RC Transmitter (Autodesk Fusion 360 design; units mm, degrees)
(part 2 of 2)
extrude "Extrusion2" cut of existing geometry blind -0.1
extrude "Extrusion3" cut of existing geometry blind -0.1
extrude "Extrusion4" cut of existing geometry blind -0.1
move "Verschieben1"
move "Verschieben2"
move "Verschieben3"
move "Verschieben4"
move "Verschieben5"
move "Verschieben6"
move_face "Fläche verschieben"
move "Verschieben7"
move "Verschieben8"
position "Position1"
sketch "Skizze1" plane through (0, 0, 23.05) normal (0, 0, 1) x axis (-1, 0, 0)
  line L1 (299.8082, 67.7452) -> (287.93, 79.6234)
  line L2 (300.1011, -67.1335) -> (300.1011, 67.0381)
  line L3 (287.894, -79.7548) -> (299.8082, -67.8406)
  line L4 (211.6011, -80.0477) -> (287.1869, -80.0477)
  line L5 (211.6011, -82.3739) -> (211.6011, -80.0477)
  line L6 (289.6007, -82.3739) -> (211.6011, -82.3739)
  line L7 (302.4261, -69.5484) -> (289.6007, -82.3739)
  line L8 (302.4261, 69.203) -> (302.4261, -69.5484)
  line L9 (289.3519, 82.2773) -> (302.4261, 69.203)
  line L10 (120.6004, 82.2773) -> (289.3519, 82.2773)
  line L11 (107.7773, 69.4542) -> (120.6004, 82.2773)
  line L12 (107.7773, -69.2973) -> (107.7773, 69.4542)
  line L13 (120.8492, -82.3739) -> (107.7773, -69.2973)
  line L14 (198.6011, -82.3739) -> (120.8492, -82.3739)
  line L15 (198.6011, -80.0477) -> (198.6011, -82.3739)
  line L16 (123.0153, -80.0477) -> (198.6011, -80.0477)
  line L17 (110.394, -67.8406) -> (122.3082, -79.7548)
  line L18 (110.1011, 67.0381) -> (110.1011, -67.1335)
  line L19 (122.2722, 79.6234) -> (110.394, 67.7452)
  line L20 (287.2229, 79.9163) -> (122.9793, 79.9163)
  line L21 (228.1104, 82.2773) -> (217.1098, 82.2773)
  line L22 (228.1104, 79.9163) -> (228.1104, 82.2773)
  line L23 (217.1098, 79.9163) -> (228.1104, 79.9163)
  line L24 (217.1098, 82.2773) -> (217.1098, 79.9163)
  arc A1 centre (299.1011, 67.0381) radius 1 clockwise from (299.8082, 67.7452) to (300.1011, 67.0381)
  arc A2 centre (299.1011, -67.1335) radius 1 clockwise from (300.1011, -67.1335) to (299.8082, -67.8406)
  arc A3 centre (287.1869, -79.0477) radius 1 clockwise from (287.894, -79.7548) to (287.1869, -80.0477)
  arc A4 centre (123.0153, -79.0477) radius 1 clockwise from (123.0153, -80.0477) to (122.3082, -79.7548)
  arc A5 centre (111.1011, -67.1335) radius 1 clockwise from (110.394, -67.8406) to (110.1011, -67.1335)
  arc A6 centre (111.1011, 67.0381) radius 1 clockwise from (110.1011, 67.0381) to (110.394, 67.7452)
  arc A7 centre (122.9793, 78.9163) radius 1 clockwise from (122.2722, 79.6234) to (122.9793, 79.9163)
  arc A8 centre (287.2229, 78.9163) radius 1 clockwise from (287.2229, 79.9163) to (287.93, 79.6234)
  point P40 (228.1104, 79.9163)
  point P38 (217.1098, 82.2773)
  horizontal L21
  vertical L22
  horizontal L23
  vertical L24
  coincident L20 P40
  coincident L10 P38
extrude "Extrusion5" cut sketch "Skizze1" profile of L10 L20 L21 L22 L23 L24 blind -5
extrude "Extrusion6" cut sketch "Skizze16" against normal blind 2.75
extrude "Extrusion7" cut sketch "Skizze16" against normal blind 4.25
extrude "Extrusion8" cut of existing geometry blind -1
extrude "Extrusion9" cut of existing geometry blind -7.5
extrude "Extrusion1" add of existing geometry blind 3
extrude "Extrusion2" cut of existing geometry blind -1.5
extrude "Extrusion3" cut of existing geometry blind -1.5
extrude "Extrusion4" cut of existing geometry blind -0.5
extrude "Extrusion5" cut of existing geometry blind -1.5
extrude "Extrusion6" add of existing geometry blind 1
fillet "Abrundung1" radius 2.5
fillet "Abrundung2" radius 1.5
fillet "Abrundung3" radius 1.5
fillet "Abrundung4" radius 1.5
extrude "Extrusion10" add of existing geometry blind 1
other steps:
base_feature "Basiselement1" bodies "Unterteil"
base_feature "Basiselement1" bodies "Oberteil"
create_component "Komponente erstellen1"
remove_body "Körper entfernen1"
create_component "Komponente erstellen2"
remove_body "Körper entfernen2"
named bodies: "Unterteil", "Oberteil"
